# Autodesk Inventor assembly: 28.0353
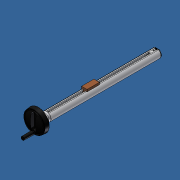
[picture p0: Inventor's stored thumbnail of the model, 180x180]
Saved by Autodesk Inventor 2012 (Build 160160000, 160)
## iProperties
Created: 2014-04
Part Number: 28.0353
Document SubType Name: Assembly
Designer: Admin
Description: MINI ADJ UNIT WITH HANDLE PROFILE 32
Vendor: F
Author: Admin
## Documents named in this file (8)
- C:\Andys Backup Data\ANDY'S INVENTOR\INVENTOR LIBRARIES\PARTS LIBRARY\READY FOR USE MODULES LG\28.0353 MINI ADJ UNIT WITH HANDLE PROFILE 32.iam
- C:\Andys Backup Data\ANDY'S INVENTOR\INVENTOR LIBRARIES\PARTS LIBRARY\READY FOR USE MODULES LG\SUBCOMPONENTS\28.0353 HANDLE PROFILE 32.ipt
- C:\Andys Backup Data\ANDY'S INVENTOR\INVENTOR LIBRARIES\PARTS LIBRARY\READY FOR USE MODULES LG\28.0350 MINI ADJ UNIT FITTING KIT.iam
- C:\Andys Backup Data\ANDY'S INVENTOR\INVENTOR LIBRARIES\PARTS LIBRARY\READY FOR USE MODULES LG\SUBCOMPONENTS\28.0367 MINI ADJ BEARING SUPPORT HANDLE 32.ipt
- C:\Andys Backup Data\ANDY'S INVENTOR\INVENTOR LIBRARIES\PARTS LIBRARY\END CAPS\22.1023_1 END CAP FOR HANDLE PROFILE 32.ipt
- C:\Andys Backup Data\ANDY'S INVENTOR\INVENTOR LIBRARIES\PARTS LIBRARY\READY FOR USE MODULES LG\SUBCOMPONENTS\28.0212 HANDWHEEL 80mm.iam
- C:\Andys Backup Data\ANDY'S INVENTOR\INVENTOR LIBRARIES\PARTS LIBRARY\READY FOR USE MODULES LG\SUBCOMPONENTS\19.0100_6 BUSHING.ipt
- C:\Andys Backup Data\ANDY'S INVENTOR\INVENTOR LIBRARIES\PARTS LIBRARY\FASTENING ELEMENTS\SCREWS CAP\21.1200 M8X16.ipt
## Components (7 placed, 7 different names)
1. 28.0353 HANDLE PROFILE 32:1 — Angle:2, Insert:3, Angle:3, Insert:4, Mate:5
2. 28.0350 MINI ADJ UNIT FITTING KIT:1 [sub-assembly] — Angle:2, Mate:3, Mate:4, Angle:5, Insert:5
3. 28.0367 MINI ADJ BEARING SUPPORT HANDLE 32:1 — Insert:4, Mate:5, Insert:5, Insert:6
4. 22.1023_1 END CAP FOR HANDLE PROFILE 32:1 — Insert:3, Angle:3
5. 28.0212 HANDWHEEL 80mm:1 [sub-assembly] — Mate:1, Angle:4, Mate:2, Mate:3, Angle:5
6. 19.0100_6 BUSHING:1 — Mate:1, Angle:4, Mate:2, Mate:4
7. 21.1200 M8 x 16:1 — Insert:6
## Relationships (13: Mate 5, Angle 4, Insert 4)
- Angle:2: 28.0353 HANDLE PROFILE 32:1 ↔ 28.0350 MINI ADJ UNIT FITTING KIT:1
- Insert:3: 28.0353 HANDLE PROFILE 32:1 ↔ 22.1023_1 END CAP FOR HANDLE PROFILE 32:1
- Angle:3: 28.0353 HANDLE PROFILE 32:1 ↔ 22.1023_1 END CAP FOR HANDLE PROFILE 32:1
- Mate:1: 28.0212 HANDWHEEL 80mm:1 ↔ 19.0100_6 BUSHING:1
- Angle:4: 28.0212 HANDWHEEL 80mm:1 ↔ 19.0100_6 BUSHING:1
- Mate:2: 28.0212 HANDWHEEL 80mm:1 ↔ 19.0100_6 BUSHING:1
- Mate:3: 28.0350 MINI ADJ UNIT FITTING KIT:1 ↔ 28.0212 HANDWHEEL 80mm:1
- Mate:4: 28.0350 MINI ADJ UNIT FITTING KIT:1 ↔ 19.0100_6 BUSHING:1
- Angle:5: 28.0350 MINI ADJ UNIT FITTING KIT:1 ↔ 28.0212 HANDWHEEL 80mm:1
- Insert:4: 28.0353 HANDLE PROFILE 32:1 ↔ 28.0367 MINI ADJ BEARING SUPPORT HANDLE 32:1
- Mate:5: 28.0353 HANDLE PROFILE 32:1 ↔ 28.0367 MINI ADJ BEARING SUPPORT HANDLE 32:1
- Insert:5: 28.0350 MINI ADJ UNIT FITTING KIT:1 ↔ 28.0367 MINI ADJ BEARING SUPPORT HANDLE 32:1
- Insert:6: 28.0367 MINI ADJ BEARING SUPPORT HANDLE 32:1 ↔ 21.1200 M8 x 16:1
